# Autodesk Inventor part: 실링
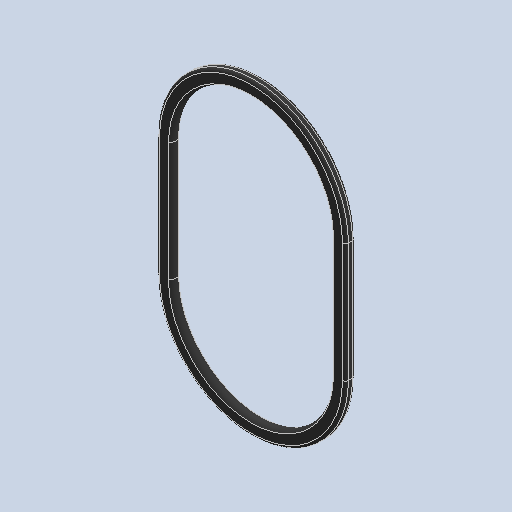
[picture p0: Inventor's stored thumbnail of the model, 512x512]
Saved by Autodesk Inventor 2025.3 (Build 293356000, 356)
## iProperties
Created: 2025-10
Part Number: 실링
Material: 고무
Document SubType Name: Modeling
Designer: PC-15
Density: 0.93 g/cm^3
Appearance: 기본값
Author: jhkim
Sending System: Autodesk Inventor 2026
Preprocessor: ST-DEVELOPER v20.1
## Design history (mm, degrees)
feature "솔리드3"
node "솔리드1"
